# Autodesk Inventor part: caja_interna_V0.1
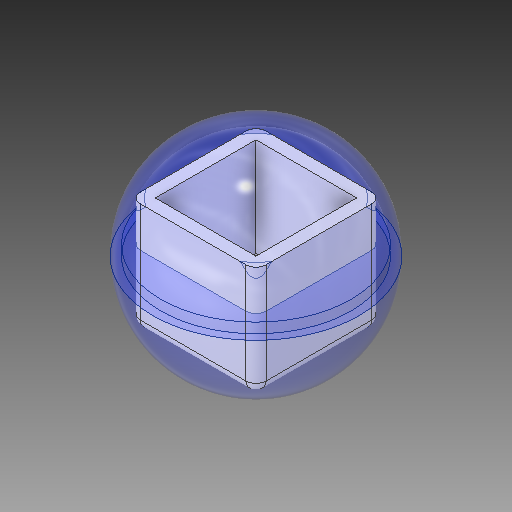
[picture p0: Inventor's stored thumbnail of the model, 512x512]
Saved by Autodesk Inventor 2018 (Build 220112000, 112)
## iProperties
Created: 2018-09
Part Number: caja_interna_V0.1
Material: Generic
Document SubType Name: Modeling
Designer: Gordillo
Density: 1 g/cm^3
Appearance: Default
Author: Gordillo
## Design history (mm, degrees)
sketch "Sketch1"
  geometry: L1 (125, 125)-(-125, 125); L2 (-125, 125)-(-125, -125); L3 (-125, -125)-(125, -125); L4 (125, -125)-(125, 125); L5 (-175, 0)-(175, 0) reference; L6 (0, -175)-(0, 175) reference; 1 further point
  constraints: 8 end point, 2 parallel, 1 horizontal, 1 perpendicular, 2 other
  dimensions: "d0" = 250 distance of L3.end L2.end; "d1" = 250 distance of L2.end L1.end
extrude "Extrusion1" new body sketch "Sketch1" distance "d2" = 220; taper "d3" = 0 deg
fillet "Fillet1" dims "d5" = 20
sketch "Sketch2"
  geometry: L1 (20, 125)-(220, 125) reference; L2 (120, 125)-(120, -125); L3 (220, -125)-(20, -125) reference; L4 (120, 125)-(120, 205); L5 (120, 0)-(-80, 0); L6 (-153.152, 0)-(282.192, 0) reference; A1 r 203.001 centre (122.991, 2.021) between (120, 205) and (-80, 0); 1 further point
  constraints: 6 end point, 3 midpoint, 2 point on circle, 1 centre point, 1 horizontal, 1 vertical
  dimensions: "d6" = 200 distance of L5.start L5.end; "d8" = 80 distance of L2.start L4.end
revolve "Revolution1" sketch "Sketch2" stored, may be unused: angle "d9" = 90 deg
combine "Combine1"
shell "Shell2" dims "d10" = 25
sketch "Sketch3"
  geometry: L1 (100, 100)-(100, -100) reference; L2 (100, -100)-(-100, -100) reference; L3 (-100, -100)-(-100, 100) reference; L4 (-100, 100)-(100, 100) reference; L5 (105, 125)-(-105, 125) reference; L6 (-125, 105)-(-125, -105) reference; L7 (-105, -125)-(105, -125) reference; L8 (125, -105)-(125, 105) reference; L9 (-105, 125)-(105, 125) reference; L10 (125, 105)-(125, -105) reference; L11 (105, -125)-(-105, -125) reference; L12 (-125, -105)-(-125, 105) reference; L13 (-105, 125)-(105, 125) reference; L14 (105, 125)-(-105, 125); L15 (-105, 125)-(-125, 105); L16 (-125, -105)-(-125, 105) reference; L17 (-125, -105)-(-105, -125); L18 (125, 105)-(125, -105) reference; L19 (105, -125)-(125, -105); L20 (125, -105)-(125, 105); L21 (-125, 105)-(-105, 105) reference; L22 (-125, 105)-(-125, -105); L23 (-105, -125)-(105, -125); C1 r 205 at (0, 0) reference; C2 r 189 at (0, 0); C3 r 205 at (0, 0) reference; A1 r 20 centre (105, 105) between (125, 105) and (105, 125) reference; A2 r 20 centre (-105, 105) between (-105, 125) and (-125, 105) reference; A3 r 20 centre (-105, -105) between (-125, -105) and (-105, -125) reference; A4 r 20 centre (105, -105) between (105, -125) and (125, -105) reference; A5 r 20 centre (-105, 105) between (-105, 125) and (-125, 105) reference; A6 r 20 centre (105, 105) between (125, 105) and (105, 125) reference; A7 r 20 centre (105, -105) between (105, -125) and (125, -105) reference; A8 r 20 centre (-105, -105) between (-125, -105) and (-105, -125) reference; A9 r 20 centre (105, 105) between (125, 105) and (105, 125) reference; A10 r 20 centre (105, 105) between (125, 105) and (105, 125); A11 r 20 centre (105, -105) between (105, -125) and (125, -105) reference; A12 r 20 centre (105, -105) between (105, -125) and (125, -105); A13 r 20 centre (-105, -105) between (-125, -105) and (-105, -125); A14 r 20 centre (-105, 105) between (-105, 125) and (-125, 105) reference; A15 r 20 centre (-105, 105) between (-105, 125) and (-125, 105); A16 r 20 centre (-105, -105) between (-125, -105) and (-105, -125); A17 r 20 centre (-105, -105) between (-125, -105) and (-105, -125); A18 r 20 centre (105, -105) between (105, -125) and (125, -105); A19 r 20 centre (-105, -105) between (-125, -105) and (-105, -125) reference; A20 r 20 centre (-105, -105) between (-125, -105) and (-105, -125); 1 further point
  constraints: 16 point on circle, 14 end point, 9 centre point, 3 perpendicular, 3 tangent, 2 collinear, 1 concentric, 1 vertical
  dimensions: "d11" = 16 radial gap between concentric circles of C1 C2
extrude "Extrusion2" join sketch "Sketch3" distance "d12" = 20; taper "d13" = 0 deg
sketch "Sketch4"
  geometry: L1 (189, 140)-(-189, 140) reference; L2 (205, 120)-(-205, 120) reference; L3 (189, 120)-(189, 140) reference; L4 (189, 140)-(-189, 140) reference; L5 (-189, 120)-(189, 120) reference; L6 (-125, 20)-(-125, 220) reference; L7 (-125, 220)-(-105, 220) reference; L8 (-205, 120)-(-189, 120); L9 (-189, 120)-(-189, 140); L10 (205, 120)-(-205, 120) reference; L11 (-189, 140)-(-125, 140); L12 (0, 120)-(0, 320); L13 (-125, 140)-(0, 140); L14 (0, -168.98)-(0, 453.807) reference; A1 r 195 centre (-10.071, 125.26) between (0, 320) and (-205, 120); A2 r 189.427 centre (-1.871, 110.582) between (0, 300) and (-189, 140); 2 further points
  constraints: 10 end point, 4 point on circle, 4 point on line, 2 centre point, 2 midpoint, 1 collinear, 1 perpendicular, 1 vertical
  dimensions: "d14" = 200 distance of L12.start L12.end; "d15" = 195 radius of A1; "d16" = 20 distance of L12.end A2.start
revolve "Revolution2" sketch "Sketch4" stored, may be unused: angle "d17" = 90 deg
combine "Combine2"
node "cajacorchopan"
node "semicirculo_inferior"
node "Projected Loop1"
node "Projected Loop2"
node "Projected Loop3"
node "Projected Loop4"
node "semicirculo_superior"
